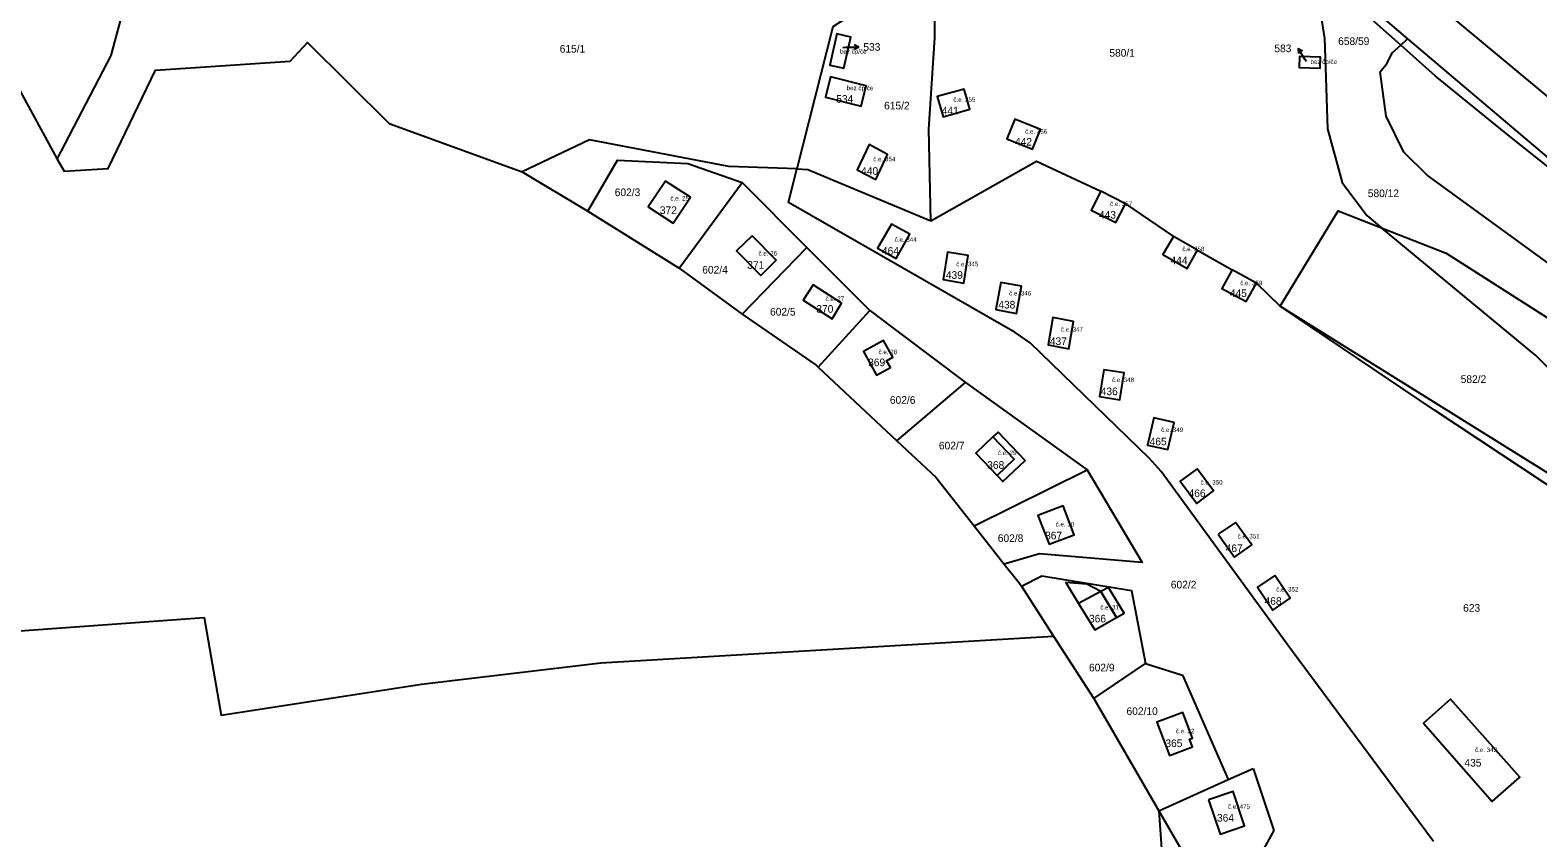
# Model space of a CAD drawing. Extents: x -887272 to -880188, y -1026687 to -1021896.
# Drawn here: x -884435.6 to -884099.9, y -1024028 to -1023848.1 of the extents above; entities that cross this region are included whole.
import ezdxf

# ---------------------------------------------------------------- set-up
doc = ezdxf.new("R2010")
doc.units = 0
for name, color, linetype in [('Definiční body', 7, 'Continuous'), ('Hranice parcel', 7, 'Continuous'), ('Parcelní čísla', 7, 'Continuous'), ('Polygon budovy', 7, 'Continuous'), ('Pop  PČ popisy', 7, 'Continuous'), ('Vnitřní kresba', 7, 'Continuous')]:
    doc.layers.add(name, color=color, linetype=linetype)

msp = doc.modelspace()

# ---------------------------------------------------------------- linework, layer by layer
at = {"layer": 'Hranice parcel'}
for p, q in [((-884130.36, -1023851.44), (-884149.84, -1023834.12)), ((-884149.84, -1023834.12), (-884147.35, -1023849.97)), ((-884130.36, -1023851.44), (-884128.87, -1023850.09)), ((-884326, -1023879.7), (-884311.37, -1023888.41)), ((-884291.02, -1023901.15), (-884277.04, -1023882.06)), ((-884277.04, -1023882.06), (-884262.61, -1023896.51)), ((-884197.18, -1023883.99), (-884199.32, -1023888.18)), ((-884191.67, -1023886.81), (-884197.18, -1023883.99)), ((-884311.37, -1023888.41), (-884291.02, -1023901.15)), ((-884199.32, -1023888.18), (-884193.8, -1023890.99)), ((-884193.8, -1023890.99), (-884191.67, -1023886.81)), ((-884191.67, -1023886.81), (-884181, -1023894.04)), ((-884175.63, -1023897.11), (-884181, -1023894.04)), ((-884277, -1023911.36), (-884262.61, -1023896.51)), ((-884262.61, -1023896.51), (-884248.57, -1023910.57)), ((-884175.63, -1023897.11), (-884167.95, -1023901.52)), ((-884291.02, -1023901.15), (-884277, -1023911.36)), ((-884162.51, -1023904.49), (-884167.95, -1023901.52)), ((-884162.51, -1023904.49), (-884157.22, -1023909.6)), ((-884260.09, -1023923.14), (-884248.57, -1023910.57)), ((-884248.57, -1023910.57), (-884227.28, -1023926.58)), ((-884260.09, -1023923.14), (-884242.57, -1023939.54)), ((-884242.57, -1023939.54), (-884227.28, -1023926.58)), ((-884227.28, -1023926.58), (-884200.19, -1023946.04)), ((-884225.38, -1023958.47), (-884200.19, -1023946.04)), ((-884225.38, -1023958.47), (-884218.65, -1023967.03)), ((-884214.86, -1023971.97), (-884207.7, -1023983.04)), ((-884207.7, -1023983.04), (-884198.73, -1023996.92)), ((-884198.73, -1023996.92), (-884187.18, -1023989.13)), ((-884198.73, -1023996.92), (-884184.24, -1024021.97)), ((-884168.78, -1024014.99), (-884163.27, -1024012.51)), ((-884163.27, -1024012.51), (-884158.67, -1024026.32)), ((-884184.24, -1024021.97), (-884168.78, -1024014.99)), ((-884184.24, -1024021.97), (-884181.13, -1024065.5))]:
    msp.add_line(p, q, dxfattribs=at)
for points in [[(-883756.5, -1024023.04), (-883767.66, -1024020.24), (-883797.06, -1024014.34), (-883842.62, -1024005.56), (-883874.8, -1024002.84), (-883906.02, -1023994.68), (-883929.04, -1023982.78), (-884005.12, -1023932.5), (-884033.98, -1023912.56), (-884080.28, -1023877.34), (-884136.58, -1023830.48), (-884162.3, -1023804.42), (-884180.14, -1023781.6), (-884204.86, -1023736.02), (-884224.62, -1023704.92), (-884247.24, -1023674.52), (-884253.66, -1023666.34), (-884254.22, -1023665.64)], [(-884429.56, -1023876.82), (-884417.56, -1023853.78), (-884411.72, -1023832.2), (-884403.24, -1023814.2), (-884403, -1023777.1)], [(-884653.42, -1023801.34), (-884649.38, -1023808.34), (-884631.54, -1023816.4), (-884609.9, -1023817.46), (-884589.9, -1023820.6), (-884567.06, -1023818.94), (-884525.36, -1023825.68), (-884479.42, -1023839.02), (-884441.42, -1023855), (-884429.56, -1023876.82)], [(-884150.38, -1023830.66), (-884142.38, -1023838.5), (-884128.87, -1023850.09)], [(-884234.22, -1023832.56), (-884256.83, -1023847.38), (-884264.84, -1023879.03)], [(-884235.04, -1023890.58), (-884235.45, -1023870.15), (-884234.12, -1023849.8), (-884234.22, -1023832.56)], [(-884255.94, -1023848.97), (-884257.49, -1023855.9), (-884254.39, -1023856.58), (-884252.82, -1023849.67), (-884255.94, -1023848.97)], [(-884429.56, -1023876.82), (-884428, -1023879.52), (-884418.2, -1023878.96), (-884407.64, -1023857.02), (-884377.7, -1023855.06), (-884373.78, -1023850.9), (-884355.62, -1023868.9), (-884326, -1023879.7)], [(-884147.35, -1023849.97), (-884147.13, -1023856.45), (-884146.67, -1023870.13), (-884143.44, -1023882.02), (-884137.94, -1023889.41), (-884134.64, -1023892.14)], [(-884042.31, -1023960.46), (-884069.15, -1023925.03), (-884088.08, -1023906.88), (-884124.51, -1023880.4), (-884129.67, -1023875.3), (-884133.64, -1023867.29), (-884134.98, -1023857.41), (-884133.42, -1023855.44), (-884132.27, -1023853.18), (-884130.36, -1023851.44)], [(-884029.85, -1023946.15), (-884027.02, -1023939.86), (-884027.86, -1023934.82), (-884029.41, -1023932.93), (-884073.28, -1023898.24), (-884085.07, -1023888.47), (-884106.9, -1023871.17), (-884122.73, -1023858.32), (-884130.36, -1023851.44)], [(-884128.87, -1023850.09), (-884088.74, -1023884.02), (-884075.38, -1023894.24), (-884039.32, -1023922.42), (-883934.44, -1023993.58), (-883913.13, -1024003.65)], [(-884148.26, -1023854.11), (-884152.91, -1023854.02), (-884152.96, -1023856.47), (-884148.32, -1023856.56), (-884148.26, -1023854.11)], [(-884249.39, -1023860.5), (-884257.34, -1023858.49), (-884258.5, -1023863.05), (-884250.54, -1023865.06), (-884249.39, -1023860.5)], [(-884232.29, -1023867.45), (-884226.36, -1023865.73), (-884227.6, -1023861.25), (-884233.57, -1023862.93), (-884232.29, -1023867.45)], [(-884210.6, -1023870.25), (-884216.34, -1023867.96), (-884218.08, -1023872.33), (-884212.34, -1023874.64), (-884210.6, -1023870.25)], [(-884264.84, -1023879.03), (-884280.02, -1023878.5), (-884311.02, -1023872.58), (-884326, -1023879.7)], [(-884244.63, -1023875.83), (-884248.78, -1023873.61), (-884251.43, -1023879.22), (-884247.27, -1023881.41), (-884244.63, -1023875.83)], [(-884311.37, -1023888.41), (-884304.81, -1023877.05), (-884289.09, -1023877.84), (-884277.04, -1023882.06)], [(-884123.06, -1024028.78), (-884154.74, -1023986.16), (-884183.74, -1023946.37), (-884186.39, -1023943.42), (-884212.89, -1023917.78), (-884216.25, -1023915.48), (-884266.73, -1023886.51), (-884264.84, -1023879.03)], [(-884264.84, -1023879.03), (-884262.42, -1023879.12), (-884235.04, -1023890.58)], [(-884235.04, -1023890.58), (-884211.48, -1023877.32), (-884197.18, -1023883.99)], [(-884292.38, -1023891.1), (-884288.53, -1023885.28), (-884294.09, -1023881.74), (-884297.98, -1023887.44), (-884292.38, -1023891.1)], [(-884157.22, -1023909.6), (-884144.28, -1023888.36), (-884134.64, -1023892.14)], [(-884239.66, -1023893.54), (-884243.79, -1023891.33), (-884246.88, -1023896.66), (-884242.74, -1023898.95), (-884239.66, -1023893.54)], [(-884134.64, -1023892.14), (-884120.26, -1023897.78), (-884074.52, -1023926.94), (-884056.83, -1023942.92), (-884042.31, -1023960.46)], [(-884032.38, -1024012.15), (-884084.32, -1023936.55), (-884100.33, -1023920.58), (-884134.64, -1023892.14)], [(-884272.86, -1023902.76), (-884269.46, -1023899.36), (-884274.8, -1023893.9), (-884278.25, -1023897.24), (-884272.86, -1023902.76)], [(-884181, -1023894.04), (-884183.35, -1023898.11), (-884177.94, -1023901.18), (-884175.63, -1023897.11)], [(-884227.66, -1023904.45), (-884226.71, -1023898.32), (-884231.3, -1023897.55), (-884232.3, -1023903.64), (-884227.66, -1023904.45)], [(-884167.95, -1023901.52), (-884170.24, -1023905.63), (-884164.8, -1023908.56), (-884162.51, -1023904.49)], [(-884261.2, -1023904.84), (-884263.42, -1023908.26), (-884256.99, -1023912.4), (-884254.88, -1023908.94), (-884261.2, -1023904.84)], [(-884215.91, -1023911.19), (-884214.85, -1023905.13), (-884219.43, -1023904.32), (-884220.52, -1023910.33), (-884215.91, -1023911.19)], [(-884277, -1023911.36), (-884260.54, -1023922.72), (-884260.09, -1023923.14)], [(-884203.22, -1023912.99), (-884207.83, -1023912.13), (-884208.89, -1023918.21), (-884204.28, -1023919.08), (-884203.22, -1023912.99)], [(-884060.68, -1023985.09), (-884069.54, -1023974.7), (-884083.38, -1023958.84), (-884122.86, -1023932.78), (-884157.22, -1023909.6)], [(-884157.22, -1023909.6), (-884084, -1023955.24), (-884061.26, -1023976.98), (-884042.7, -1024003.23), (-884032.38, -1024012.15)], [(-884244.03, -1023923.24), (-884244.85, -1023921.75), (-884243.45, -1023920.98), (-884245.53, -1023917.21), (-884250, -1023919.68), (-884247.1, -1023924.93), (-884244.03, -1023923.24)], [(-884197.48, -1023929.74), (-884192.92, -1023930.48), (-884191.94, -1023924.45), (-884196.52, -1023923.74), (-884197.48, -1023929.74)], [(-884611.41, -1023929.67), (-884543.95, -1023947.86), (-884493.42, -1023970.29), (-884469.6, -1023978.94), (-884462.29, -1023980.71), (-884451.21, -1023982.83), (-884396.84, -1023978.9), (-884393.01, -1024000.69), (-884348.42, -1023993.73), (-884308.47, -1023988.98), (-884207.7, -1023983.04)], [(-884182.23, -1023941.53), (-884180.8, -1023935.51), (-884185.35, -1023934.43), (-884186.77, -1023940.54), (-884182.23, -1023941.53)], [(-884242.57, -1023939.54), (-884233.88, -1023947.68), (-884225.38, -1023958.47)], [(-884221.17, -1023938.71), (-884224.96, -1023942.32), (-884220.23, -1023947.29), (-884218.97, -1023948.62), (-884213.99, -1023943.96), (-884220.02, -1023937.62), (-884221.17, -1023938.71)], [(-884200.19, -1023946.04), (-884187.93, -1023966.68), (-884210.82, -1023964.71), (-884218.65, -1023967.03)], [(-884175.79, -1023953.56), (-884172.1, -1023950.72), (-884175.72, -1023945.78), (-884179.49, -1023948.58), (-884175.79, -1023953.56)], [(-884208.64, -1023962.56), (-884203.06, -1023960.52), (-884205.56, -1023954.08), (-884211.18, -1023956.2), (-884208.64, -1023962.56)], [(-884171.02, -1023960.39), (-884167.43, -1023965.48), (-884163.57, -1023962.76), (-884167.17, -1023957.75), (-884171.02, -1023960.39)], [(-884218.65, -1023967.03), (-884215.36, -1023971.2), (-884214.86, -1023971.97)], [(-884214.86, -1023971.97), (-884210.28, -1023969.65), (-884190.36, -1023972.93), (-884187.18, -1023989.13)], [(-884158.4, -1023969.59), (-884162.31, -1023972.13), (-884158.84, -1023977.32), (-884155.01, -1023974.6), (-884158.4, -1023969.59)], [(-884202.1, -1023975.78), (-884198.52, -1023981.64), (-884193.65, -1023978.88), (-884191.99, -1023977.94), (-884195.48, -1023972.27), (-884197.16, -1023973.16), (-884200.26, -1023971.52), (-884204.94, -1023971.14), (-884202.1, -1023975.78)], [(-884187.18, -1023989.13), (-884178.95, -1023991.73), (-884168.78, -1024014.99)], [(-884176.77, -1024005.79), (-884178.92, -1024000.06), (-884184.68, -1024002.22), (-884181.89, -1024009.67), (-884176.78, -1024007.75), (-884177.42, -1024006.04), (-884176.77, -1024005.79)], [(-884125.34, -1024002.46), (-884110, -1024019.9), (-884103.88, -1024014.49), (-884119.27, -1023997.12), (-884125.34, -1024002.46)], [(-884173.17, -1024019.49), (-884170.61, -1024027.19), (-884165.18, -1024025.34), (-884167.72, -1024017.67), (-884173.17, -1024019.49)], [(-884184.24, -1024021.97), (-884171.36, -1024044.23), (-884163.4, -1024055.98)], [(-884158.67, -1024026.32), (-884167.73, -1024042.82), (-884163.4, -1024055.98)]]:
    msp.add_lwpolyline(points, dxfattribs=at)
at = {"layer": 'Polygon budovy'}
for points in [[(-884257.49, -1023855.9), (-884254.39, -1023856.58), (-884252.82, -1023849.67), (-884255.94, -1023848.97)], [(-884152.91, -1023854.02), (-884152.96, -1023856.47), (-884148.32, -1023856.56), (-884148.26, -1023854.11)], [(-884257.34, -1023858.49), (-884258.5, -1023863.05), (-884250.54, -1023865.06), (-884249.39, -1023860.5)], [(-884233.57, -1023862.93), (-884232.29, -1023867.45), (-884226.36, -1023865.73), (-884227.6, -1023861.25)], [(-884216.34, -1023867.96), (-884218.08, -1023872.33), (-884212.34, -1023874.64), (-884210.6, -1023870.25)], [(-884248.78, -1023873.61), (-884251.43, -1023879.22), (-884247.27, -1023881.41), (-884244.63, -1023875.83)], [(-884297.98, -1023887.44), (-884292.38, -1023891.1), (-884288.53, -1023885.28), (-884294.09, -1023881.74)], [(-884197.18, -1023883.99), (-884199.32, -1023888.18), (-884193.8, -1023890.99), (-884191.67, -1023886.81)], [(-884243.79, -1023891.33), (-884246.88, -1023896.66), (-884242.74, -1023898.95), (-884239.66, -1023893.54)], [(-884269.46, -1023899.36), (-884274.8, -1023893.9), (-884278.25, -1023897.24), (-884272.86, -1023902.76)], [(-884181, -1023894.04), (-884183.35, -1023898.11), (-884177.94, -1023901.18), (-884175.63, -1023897.11)], [(-884231.3, -1023897.55), (-884232.3, -1023903.64), (-884227.66, -1023904.45), (-884226.71, -1023898.32)], [(-884167.95, -1023901.52), (-884170.24, -1023905.63), (-884164.8, -1023908.56), (-884162.51, -1023904.49)], [(-884254.88, -1023908.94), (-884261.2, -1023904.84), (-884263.42, -1023908.26), (-884256.99, -1023912.4)], [(-884219.43, -1023904.32), (-884220.52, -1023910.33), (-884215.91, -1023911.19), (-884214.85, -1023905.13)], [(-884207.83, -1023912.13), (-884208.89, -1023918.21), (-884204.28, -1023919.08), (-884203.22, -1023912.99)], [(-884243.45, -1023920.98), (-884245.53, -1023917.21), (-884250, -1023919.68), (-884247.1, -1023924.93), (-884244.03, -1023923.24), (-884244.85, -1023921.75)], [(-884196.52, -1023923.74), (-884197.48, -1023929.74), (-884192.92, -1023930.48), (-884191.94, -1023924.45)], [(-884185.35, -1023934.43), (-884186.77, -1023940.54), (-884182.23, -1023941.53), (-884180.8, -1023935.51)], [(-884224.96, -1023942.32), (-884220.23, -1023947.29), (-884216.43, -1023943.69), (-884221.17, -1023938.71)], [(-884179.49, -1023948.58), (-884175.79, -1023953.56), (-884172.1, -1023950.72), (-884175.72, -1023945.78)], [(-884211.18, -1023956.2), (-884208.64, -1023962.56), (-884203.06, -1023960.52), (-884205.56, -1023954.08)], [(-884171.02, -1023960.39), (-884167.43, -1023965.48), (-884163.57, -1023962.76), (-884167.17, -1023957.75)], [(-884158.4, -1023969.59), (-884162.31, -1023972.13), (-884158.84, -1023977.32), (-884155.01, -1023974.6)], [(-884202.1, -1023975.78), (-884198.52, -1023981.64), (-884193.65, -1023978.88), (-884197.16, -1023973.16)], [(-884178.92, -1024000.06), (-884184.68, -1024002.22), (-884181.89, -1024009.67), (-884176.78, -1024007.75), (-884177.42, -1024006.04), (-884176.77, -1024005.79)], [(-884119.27, -1023997.12), (-884125.34, -1024002.46), (-884110, -1024019.9), (-884103.88, -1024014.49)], [(-884173.17, -1024019.49), (-884170.61, -1024027.19), (-884165.18, -1024025.34), (-884167.72, -1024017.67)]]:
    msp.add_lwpolyline(points, close=True, dxfattribs=at)
at = {"layer": 'Pop  PČ popisy'}
for p, q in [((-884254.64, -1023851.95), (-884254.04, -1023851.93)), ((-884254.04, -1023851.93), (-884251.04, -1023851.88)), ((-884251.04, -1023851.88), (-884252.05, -1023851.39)), ((-884251.04, -1023851.88), (-884252.03, -1023852.4)), ((-884151.65, -1023854.72), (-884153.24, -1023852.18)), ((-884153.24, -1023852.18), (-884152.29, -1023852.76)), ((-884153.24, -1023852.18), (-884153.13, -1023853.29)), ((-884151.39, -1023855.13), (-884151.65, -1023854.72))]:
    msp.add_line(p, q, dxfattribs=at)
at = {"layer": 'Vnitřní kresba'}
for p, q in [((-884216.43, -1023943.69), (-884221.17, -1023938.71)), ((-884220.23, -1023947.29), (-884216.43, -1023943.69)), ((-884197.16, -1023973.16), (-884202.1, -1023975.78)), ((-884197.16, -1023973.16), (-884193.65, -1023978.88))]:
    msp.add_line(p, q, dxfattribs=at)

# ---------------------------------------------------------------- texts
at = {"layer": 'Definiční body'}
for s, p in [('bez čp/če', (-884255.23, -1023853.39)), ('bez čp/če', (-884150.48, -1023855.65)), ('bez čp/če', (-884253.74, -1023861.5)), ('č.e. 355', (-884230, -1023864.08)), ('č.e. 356', (-884214.01, -1023871.17)), ('č.e. 354', (-884247.83, -1023877.32)), ('č.e. 25', (-884293.01, -1023886.07)), ('č.e. 357', (-884195.08, -1023887.29)), ('č.e. 344', (-884243.07, -1023895.25)), ('č.e. 26', (-884273.38, -1023898.32)), ('č.e. 358', (-884179.01, -1023897.34)), ('č.e. 345', (-884229.36, -1023900.71)), ('č.e. 346', (-884217.58, -1023907.21)), ('č.e. 359', (-884166.11, -1023904.93)), ('č.e. 27', (-884258.46, -1023908.43)), ('č.e. 347', (-884206.06, -1023915.27)), ('č.e. 28', (-884246.66, -1023920.28)), ('č.e. 348', (-884194.67, -1023926.49)), ('č.e. 349', (-884183.73, -1023937.61)), ('č.e. 29', (-884220.08, -1023942.74)), ('č.e. 350', (-884174.95, -1023949.31)), ('č.e. 30', (-884207.22, -1023958.65)), ('č.e. 351', (-884166.7, -1023961.32)), ('č.e. 352', (-884158.09, -1023973.13)), ('č.e. 31', (-884197.27, -1023977.13)), ('č.e. 32', (-884180.48, -1024004.69)), ('č.e. 343', (-884113.84, -1024008.88)), ('č.e. 475', (-884168.87, -1024021.52))]:
    msp.add_text(s, height=1, dxfattribs=at).set_placement(p)
at = {"layer": 'Parcelní čísla'}
for s, p in [('615/1', (-884317.65, -1023853.13)), ('533', (-884250.04, -1023852.71)), ('580/1', (-884195.26, -1023854.03)), ('583', (-884158.52, -1023853.03)), ('658/59', (-884144.32, -1023851.43)), ('534', (-884256.08, -1023864.29)), ('615/2', (-884245.42, -1023865.77)), ('441', (-884232.58, -1023866.88)), ('442', (-884216.28, -1023873.83)), ('440', (-884250.54, -1023880.34)), ('602/3', (-884305.4, -1023885.08)), ('580/12', (-884137.71, -1023885.3)), ('372', (-884295.35, -1023889.07)), ('443', (-884197.58, -1023890.09)), ('464', (-884245.9, -1023898.13)), ('444', (-884181.65, -1023900.24)), ('602/4', (-884285.91, -1023902.33)), ('371', (-884275.89, -1023901.27)), ('439', (-884231.67, -1023903.5)), ('445', (-884168.44, -1023907.56)), ('370', (-884260.51, -1023911.05)), ('438', (-884219.99, -1023910.11)), ('602/5', (-884270.82, -1023911.68)), ('437', (-884208.51, -1023918.24)), ('369', (-884248.97, -1023922.95)), ('582/2', (-884117.03, -1023926.69)), ('602/6', (-884244.13, -1023931.33)), ('436', (-884197.19, -1023929.41)), ('602/7', (-884233.21, -1023941.48)), ('465', (-884186.29, -1023940.58)), ('368', (-884222.46, -1023945.81)), ('466', (-884177.63, -1023952.1)), ('367', (-884209.57, -1023961.51)), ('602/8', (-884220.1, -1023962.1)), ('467', (-884169.36, -1023964.35)), ('602/2', (-884181.57, -1023972.45)), ('468', (-884160.7, -1023976.09)), ('623', (-884116.48, -1023977.64)), ('366', (-884199.8, -1023980.01)), ('602/9', (-884199.79, -1023990.91)), ('602/10', (-884191.44, -1024000.63)), ('365', (-884182.79, -1024007.77)), ('435', (-884116.2, -1024012.11)), ('364', (-884171.3, -1024024.37))]:
    msp.add_text(s, height=1.7, dxfattribs=at).set_placement(p)

doc.saveas('drawing.dxf')
